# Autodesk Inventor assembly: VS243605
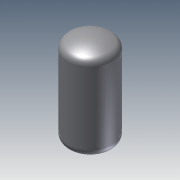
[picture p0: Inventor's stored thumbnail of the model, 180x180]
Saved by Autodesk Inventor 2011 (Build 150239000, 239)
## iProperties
Created: 2010-06
Part Number: VS243605
Document SubType Name: Assembly
Designer: mklassen
OD: 24.000 in
THK: 0.500 in
LEN: 3.000 ft
Author: mklassen
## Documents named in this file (3)
- O:\cadd\tutorials\inventor 2011\iLogic\VS243605.iam
- O:\cadd\tutorials\inventor 2011\iLogic\Shell-01.ipt
- O:\cadd\tutorials\inventor 2011\iLogic\Head-01.ipt
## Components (3 placed, 2 different names)
1. Shell-01:1 — Flush:5, Mate:1, Mate:2
2. Head-01:1
3. Head-01:2
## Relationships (3: Mate 2, Flush 1)
- Flush:5: Shell-01:1
- Mate:1: Shell-01:1
- Mate:2: Shell-01:1
